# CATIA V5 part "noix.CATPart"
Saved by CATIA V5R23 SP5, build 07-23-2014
Part number: noix
Definition: noix
Source: made
Bounding box of the stored display mesh (mm): x 201 to 221, y -24 to 24, z -40 to 40
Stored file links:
  C:\wamp\www\COURS\CONCEPTION GMP1\TITRE 01-CATIA VOLUMIQUE\05--ACTIONNEUR DE VANNE\prof\CORRECTION\Assemblage\noix.CATPart
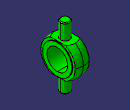
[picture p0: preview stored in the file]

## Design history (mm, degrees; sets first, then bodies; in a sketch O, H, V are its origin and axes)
Set1
  Plane1: type Offset, RefPlane face of Solid1, Offset 40
Body1 "NONE" (main body)
  Solid1 "Manifold Solid #2875": solid without history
